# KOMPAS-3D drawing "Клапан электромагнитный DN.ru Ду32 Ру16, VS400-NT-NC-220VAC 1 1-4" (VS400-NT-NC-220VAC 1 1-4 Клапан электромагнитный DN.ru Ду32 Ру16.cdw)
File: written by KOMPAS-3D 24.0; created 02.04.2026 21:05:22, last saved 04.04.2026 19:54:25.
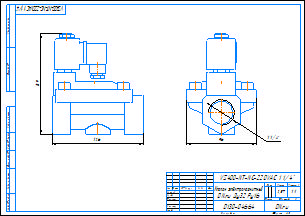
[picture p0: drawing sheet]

Document properties: c3d_UniqueCompID: ef56311e-7521-43dc-8291-0e6108b3d81d; Обозначение: VS400-ET-NC-220VAC 1; Наименование: Клапан электромагнитный DN.ru Ду25 Ру16; Автор: artio; Класс точности: c; Знак неуказанной шероховатости: Шероховатость не задана; Рассекать на разрезах: Да; c3d_UniqueCompID: ef56311e-7521-43dc-8291-0e6108b3d81d; Обозначение: VS400-ET-NC-220VAC 1-2; Наименование: Клапан электромагнитный DN.ru Ду15 Ру16; Автор: artio; Класс точности: c; Знак неуказанной шероховатости: Шероховатость не задана; Рассекать на разрезах: Да; c3d_UniqueCompID: ef56311e-7521-43dc-8291-0e6108b3d81d; Обозначение: VS400-ET-NC-220VAC 3-4; Наименование: Клапан электромагнитный DN.ru Ду20 Ру16; Автор: artio; Класс точности: c; Знак неуказанной шероховатости: Шероховатость не задана; Рассекать на разрезах: Да; c3d_UniqueCompID: ef56311e-7521-43dc-8291-0e6108b3d81d; Обозначение: VS400-ET-NC-220VAC 1 1-4; Наименование: Клапан электромагнитный DN.ru Ду32 Ру16; Автор: artio; Класс точности: c; Знак неуказанной шероховатости: Шероховатость не задана; Рассекать на разрезах: Да; c3d_UniqueCompID: ef56311e-7521-43dc-8291-0e6108b3d81d; Обозначение: VS400-ET-NC-220VAC 3-8; Наименование: Клапан электромагнитный DN.ru Ду10 Ру16; Автор: artio; Класс точности: c; Знак неуказанной шероховатости: Шероховатость не задана; Рассекать на разрезах: Да; Автор: artio; Форматы листов документа: A3; Полное имя файла: VS400-NT-NC-220VAC 1 1-4 Клапан электромагнитный DN.ru Ду32 Ру16.m3d; Масса: 2.569; Наименование: Клапан электромагнитный DN.ru Ду32 Ру16; Количество листов документа: 1; Примечание: D130-04664

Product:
- Body: Тело 1  | qty 1
    Масса: 4.144257
- Part/product: Клапан электромагнитный DN.ru Ду32 Ру16  | designation VS400-NT-NC-220VAC 1 1-4
    Масса: 2.569
    Раздел спецификации: Прочие изделия
    Примечание: D130-04664
    additional columns: ef56311e-7521-43dc-8291-0e6108b3d81d; VS400-ET-NC-220VAC 1 1-4; artio; c; Шероховатость не задана; Да

Views: Вид 1, Спереди
Referenced files in C:\Users\artio\OneDrive\Рабочий стол\Клапан электромагнитный DN.ru VS4x-xT-NC-x\DN10\: VS400-ET-NC-220VAC 3-8 Клапан электромагнитный DN.ru Ду10 Ру16.m3d, VS400-ET-NC-220VAC 3-8 Клапан электромагнитный DN.ru Ду10 Ру16.cdw
Referenced files in C:\Users\artio\OneDrive\Рабочий стол\Клапан электромагнитный DN.ru\VS400-NT-NC\VS400-NT-NC-220VAC\: VS400-NT-NC-220VAC 1 1-4 Клапан электромагнитный DN.ru Ду32 Ру16.m3d
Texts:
  VS400-NT-NC-220VAC 1 1-4
  Клапан электромагнитный
  DN.ru Ду32 Ру16
  VS400-NT-NC-220VAC 1 1/4"
  VS400-NT-NC-220VAC 1 1/4"-
  Клапан электромагнитный DN.ru Ду32 Ру16
  VS400-NT-NC-220VAC 1 1-4 Клапан электромагнитный DN.ru Ду32 Ру16
Dimensions and other numbers on the sheet: 0; 3; 2; 4; 96; 1 1/4"; 1:1; 1; 2,57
